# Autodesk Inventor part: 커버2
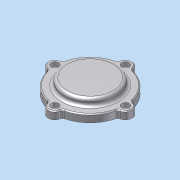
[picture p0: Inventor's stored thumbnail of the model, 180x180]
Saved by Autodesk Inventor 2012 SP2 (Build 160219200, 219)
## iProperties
Company: 한국ATC센터
Created: 2015-03
Part Number: 커버2
Document SubType Name: Modeling
Designer: KYOUNG IL JANG
Density: 1 g/cm^3
Material: 기본값
Author: KYOUNG IL JANG
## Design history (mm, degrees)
sketch "스케치1"
  geometry: C1 r 1.621 at (0, 6.75) reference; C2 r 1.621 at (-37, -30.25) reference; C3 r 1.621 at (0, -67.25) reference; C4 r 1.621 at (37, -30.25) reference; C5 r 10 at (0, -30.25) reference; C6 r 12 at (0, -30.25); C7 r 24.5 at (0, -30.25) reference; A1 r 3 centre (-38.77, -20.408) between (-38.239, -23.361) and (-35.862, -21.146) reference; A2 r 7 centre (-37, -30.25) between (-38.239, -23.361) and (-38.239, -37.139) reference; A3 r 3 centre (-38.77, -40.092) between (-35.862, -39.354) and (-38.239, -37.139) reference; A4 r 37 centre (0, -30.25) between (-35.862, -39.354) and (-9.104, -66.113) reference; A5 r 3 centre (-9.842, -69.02) between (-6.889, -68.489) and (-9.104, -66.113) reference; A6 r 7 centre (0, -67.25) between (-6.889, -68.489) and (6.889, -68.489) reference; A7 r 3 centre (9.842, -69.02) between (9.104, -66.112) and (6.889, -68.489) reference; A8 r 37 centre (0, -30.25) between (9.104, -66.112) and (35.863, -39.354) reference; A9 r 3 centre (38.77, -40.092) between (38.239, -37.139) and (35.863, -39.354) reference; A10 r 7 centre (37, -30.25) between (38.239, -37.139) and (38.239, -23.361) reference; A11 r 3 centre (38.77, -20.408) between (35.863, -21.146) and (38.239, -23.361) reference; A12 r 37 centre (0, -30.25) between (35.863, -21.146) and (9.104, 5.612) reference; A13 r 3 centre (9.842, 8.52) between (6.889, 7.989) and (9.104, 5.612) reference; A14 r 7 centre (0, 6.75) between (6.889, 7.989) and (-6.889, 7.989) reference; A15 r 3 centre (-9.842, 8.52) between (-9.104, 5.612) and (-6.889, 7.989) reference; A16 r 37 centre (0, -30.25) between (-9.104, 5.612) and (-35.862, -21.146) reference; 1 further point
  constraints: 1 centre point, 1 coincident
  dimensions: "d2" = 2 radial gap between concentric circles of C6 C5
extrude "돌출1" new body sketch "스케치1" distance "d0" = 8; taper "d1" = 0 deg
sketch "스케치2"
  geometry: C1 r 23.5 at (0, -30.25) reference; C2 r 12 at (0, -30.25) reference; 1 further point
extrude "돌출2" join sketch "스케치2" distance "d4" = 5; taper "d5" = 0 deg
sketch "스케치3"
  geometry: C1 r 23.5 at (0, 0) reference; C2 r 20.5 at (0, 0); 1 further point
  constraints: 1 centre point
  dimensions: "d6" = 3 radial gap between concentric circles of C2 C1
node "작업 평면1"
extrude "돌출3" join sketch "스케치3" stored distance "d7" = 5; taper "d8" = 0 deg
fillet "모깎기1" dims "d9" = 3
sketch "스케치4"
  geometry: C1 r 12 at (0, -30.25) reference; C2 r 27 at (0, -30.25); 1 further point
  constraints: 1 centre point
  dimensions: "d10" = 15 radial gap between concentric circles of C1 C2
extrude "돌출4" join sketch "스케치4" distance "d11" = 7; taper "d12" = 0 deg
fillet "모깎기2" dims "d13" = 3
chamfer "모따기1" distance "d14" = 1; stored, may be unused: second distance "d15" = 2, angle "d16" = 45 deg
node "작업점1"
  node "작업축1"
chamfer "모따기2" distance "d24" = 1; stored, may be unused: second distance "d25" = 2, angle "d26" = 45 deg
hole "구멍6" diameter "d43" = 4.5; stored, may be unused: countersink angle "d47" = 90 deg, drill point angle "d49" = 118 deg; dims "d41" = 10, "d42" = 10, "d44" = 6, "d45" = 8, "d46" = 4.4, "d48" = 8
fillet "모깎기4" dims "d60" = 3
node "솔리드1"
pattern_circular "원형 패턴1" dims angle "d51" = 360 deg
node "참조1"
node "참조2"
